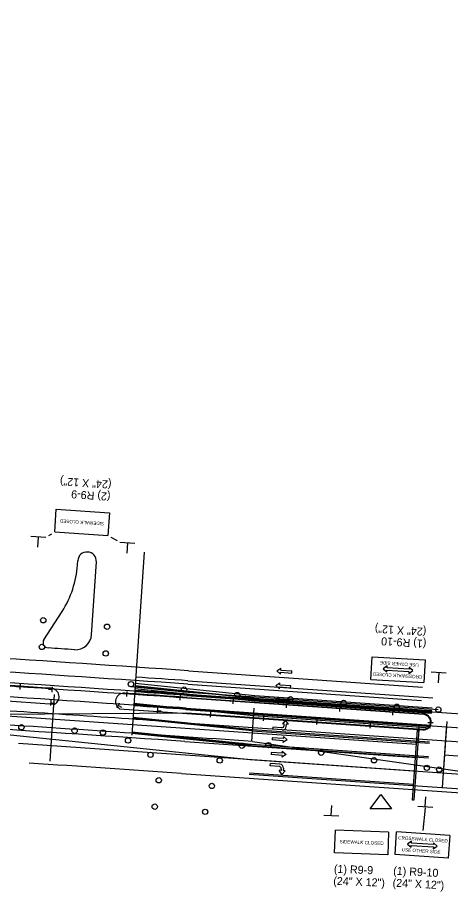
# Model space of a CAD drawing. Extents: x 659657 to 668193, y 633084 to 648639.
# Drawn here: x 660807 to 661132, y 642379 to 643043 of the extents above; entities that cross this region are included whole.
import ezdxf

# ---------------------------------------------------------------- set-up
doc = ezdxf.new("R2010")
doc.units = 0
for name, color, linetype in [('R_Draft', 7, 'Continuous'), ('R_MOT_Stage 2', 7, 'Continuous'), ('R_MOT_Stage 2_Striping', 7, 'Continuous'), ('R_MOT_Stage 3', 7, 'Continuous'), ('R_MOT_Stage 3_Striping', 7, 'Continuous'), ('R_MOT_Stage 4', 7, 'Continuous'), ('R_MOT_Stage 4_Striping', 7, 'Continuous'), ('R_MOT_Stage 4_Striping_PPM', 7, 'Continuous'), ('R_MOT_Stage 5', 7, 'Continuous'), ('R_MOT_Stage 5_Striping', 7, 'Continuous'), ('R_MOT_Stage 5_Striping_PPM', 7, 'Continuous'), ('R_ROW Annot', 7, 'Continuous'), ('T_Notes', 7, 'Continuous'), ('T_SIGNAL CONTROL CABINET', 7, 'Continuous')]:
    doc.layers.add(name, color=color, linetype=linetype)

msp = doc.modelspace()

# ---------------------------------------------------------------- linework, layer by layer
at = {"layer": 'R_Draft'}
for p, q in [((661072.13, 642547.16), (661073.2, 642564.14)), ((661073.2, 642564.14), (661112.98, 642561.65)), ((661112.98, 642561.65), (661111.92, 642544.68)), ((661117.44, 642552.85), (661128.67, 642552.15)), ((661123.01, 642552.34), (661122.54, 642544.67)), ((661072.13, 642547.16), (661111.92, 642544.68)), ((661042.54, 642445.15), (661042.84, 642452.82)), ((661048.13, 642444.77), (661036.89, 642445.21)), ((661044.96, 642417.35), (661045.62, 642434.34)), ((661085.45, 642432.81), (661045.62, 642434.34)), ((661085.45, 642432.81), (661084.79, 642415.81)), ((661084.79, 642415.81), (661044.96, 642417.35))]:
    msp.add_line(p, q, dxfattribs=at)
msp.add_lwpolyline([(661103.73, 642553.71), (661100.96, 642556.13), (661100.87, 642554.73), (661084.35, 642555.76), (661084.44, 642557.17), (661081.38, 642555.1), (661084.16, 642552.68), (661084.24, 642554.08), (661100.76, 642553.05), (661100.68, 642551.64)], close=True, dxfattribs=at)
at = {"layer": 'R_MOT_Stage 2'}
for centre in [(660810.22, 642511.3), (660850.14, 642508.74), (660871.33, 642507.33), (660890.14, 642501.35), (660975.54, 642497.5), (660995.36, 642497.86), (660907.03, 642490.63), (661034.95, 642492.21), (660958.88, 642486.43), (661074.55, 642486.56), (661114.15, 642480.92), (661123.44, 642479.59), (660913.2, 642471.61), (660952.95, 642467.33), (660910.18, 642451.84), (660948, 642447.95)]:
    msp.add_circle(centre, 2, dxfattribs=at)
at = {"layer": 'R_MOT_Stage 2_Striping'}
for p, q in [((660935.07, 642546.09), (661118.74, 642533.32)), ((660934.3, 642535.11), (661117.98, 642522.34)), ((660934.37, 642536.11), (661118.05, 642523.34)), ((660933.58, 642524.64), (661117.25, 642511.87)), ((660933.65, 642525.64), (661117.32, 642512.87)), ((660932.88, 642514.66), (661237.48, 642493.49)), ((660983.54, 642500.56), (661138.84, 642478.4)), ((661127.39, 642490.62), (661236.8, 642483.01))]:
    msp.add_line(p, q, dxfattribs=at)
for radius, start, end in [(22935.31, 86.023046, 86.121408), (22924.31, 86.023046, 86.121408), (22925.31, 86.023046, 86.121408), (22903.81, 86.023046, 86.444357), (22913.81, 86.023046, 86.121408), (22914.81, 86.023046, 86.121408), (22893.31, 85.894127, 86.444357)]:
    msp.add_arc((659344.38, 619666), radius, start, end, dxfattribs=at)
at = {"layer": 'R_MOT_Stage 3'}
for p, q in [((660895.48, 642544.22), (660985.14, 642535.09)), ((660985, 642533.09), (660895.34, 642542.23)), ((660985, 642533.09), (661117.88, 642523.85)), ((660985.14, 642535.09), (661118.02, 642525.85))]:
    msp.add_line(p, q, dxfattribs=at)
for centre in [(660826.63, 642591.39), (660874.44, 642586.52), (660825.62, 642571.41), (660873.43, 642566.55), (660892.38, 642543.53), (660932.17, 642539.48), (660971.97, 642535.43), (661011.87, 642532.23), (661051.77, 642529.45), (661091.67, 642526.68), (661122.73, 642524.52)]:
    msp.add_circle(centre, 2, dxfattribs=at)
at = {"layer": 'R_MOT_Stage 3_Striping'}
for p, q in [((660895.21, 642540.24), (660984.86, 642531.11)), ((660984.86, 642531.1), (661117.75, 642521.86)), ((660894.46, 642529.26), (660984.1, 642520.12)), ((660983.3, 642508.65), (660893.68, 642517.78)), ((660893.75, 642518.78), (660983.37, 642509.65)), ((660984.1, 642520.12), (661116.98, 642510.89)), ((660768.15, 642508.98), (660981.81, 642487.2)), ((660892.94, 642506.81), (660982.54, 642497.68)), ((660893.01, 642507.81), (660982.6, 642498.68)), ((660983.3, 642508.65), (661116.18, 642499.41)), ((660983.37, 642509.65), (661116.25, 642500.41)), ((660982.54, 642497.68), (661115.42, 642488.44)), ((660982.6, 642498.68), (661115.49, 642489.44)), ((660981.81, 642487.2), (661235.75, 642469.55)), ((660981.04, 642476.23), (661234.99, 642458.58))]:
    msp.add_line(p, q, dxfattribs=at)
at = {"layer": 'R_MOT_Stage 4'}
for p, q in [((660895.48, 642544.22), (660985.14, 642535.09)), ((660895.34, 642542.23), (660985, 642533.09)), ((660985, 642533.09), (661117.88, 642523.85)), ((660985.14, 642535.09), (661118.02, 642525.85))]:
    msp.add_line(p, q, dxfattribs=at)
for centre in [(660826.63, 642591.39), (660874.44, 642586.52), (660825.62, 642571.41), (660873.43, 642566.55), (660892.38, 642543.53), (660932.17, 642539.48), (660971.97, 642535.43), (661011.87, 642532.23), (661051.77, 642529.45), (661091.67, 642526.68), (661122.73, 642524.52)]:
    msp.add_circle(centre, 2, dxfattribs=at)
at = {"layer": 'R_MOT_Stage 4_Striping'}
for p, q in [((660895.21, 642540.24), (660985.11, 642531.08)), ((660985.11, 642531.08), (661117.75, 642521.86)), ((660894.46, 642529.26), (660984.1, 642520.12)), ((660983.3, 642508.65), (660893.68, 642517.78)), ((660893.75, 642518.78), (660983.37, 642509.65)), ((660984.1, 642520.12), (661116.98, 642510.89)), ((660768.15, 642508.98), (660981.81, 642487.2)), ((660982.54, 642497.68), (660892.94, 642506.81)), ((660893.01, 642507.81), (660982.6, 642498.68)), ((660983.3, 642508.65), (661116.18, 642499.41)), ((660983.37, 642509.65), (661116.25, 642500.41)), ((660982.54, 642497.68), (661115.42, 642488.44)), ((660982.6, 642498.68), (661115.49, 642489.44)), ((660981.81, 642487.2), (661235.75, 642469.55)), ((660981.04, 642476.23), (661235.44, 642458.55))]:
    msp.add_line(p, q, dxfattribs=at)
at = {"layer": 'R_MOT_Stage 4_Striping_PPM'}
msp.add_arc((660777.38, 642087.58), 954.93, 348.72774, 348.72774, dxfattribs=at)
at = {"layer": 'R_MOT_Stage 5'}
for p, q in [((660809.21, 642541.46), (660806.5, 642541.64)), ((660809.4, 642543.43), (660809.14, 642539.46)), ((660833.2, 642539.47), (660830.49, 642539.65)), ((660833.38, 642541.44), (660833.12, 642537.47)), ((660889.23, 642538.18), (660888.96, 642534.21)), ((660832.29, 642527.58), (660832.53, 642531.55)), ((660889.04, 642536.21), (660886.33, 642536.39)), ((660928.95, 642533.48), (660926.24, 642533.67)), ((660929.14, 642535.45), (660928.87, 642531.48)), ((660968.85, 642530.71), (660966.14, 642530.9)), ((660969.04, 642532.68), (660968.77, 642528.71)), ((660832.46, 642529.55), (660835.18, 642529.38)), ((660881.96, 642525.93), (660883.8, 642529.46)), ((660882.93, 642527.66), (660885.34, 642526.41)), ((660912.14, 642521.79), (660912.38, 642525.76)), ((660912.31, 642523.76), (660915.03, 642523.6)), ((661008.75, 642527.93), (661006.04, 642528.12)), ((661008.95, 642529.9), (661008.67, 642525.93)), ((661048.66, 642525.16), (661045.95, 642525.35)), ((661048.85, 642527.13), (661048.58, 642523.16)), ((661088.76, 642524.36), (661088.48, 642520.39)), ((660951.91, 642518.87), (660952.18, 642522.84)), ((660952.1, 642520.85), (660954.81, 642520.66)), ((660991.81, 642516.1), (660992.09, 642520.07)), ((660992.01, 642518.07), (660994.72, 642517.88)), ((661031.72, 642513.33), (661031.99, 642517.3)), ((661088.56, 642522.38), (661085.85, 642522.57)), ((661031.91, 642515.3), (661034.62, 642515.11)), ((661071.62, 642510.55), (661071.9, 642514.52)), ((661071.81, 642512.52), (661074.52, 642512.33)), ((661108.05, 642508.02), (661108.33, 642511.99)), ((661114.98, 642514.97), (661118.96, 642514.94)), ((661116.96, 642514.9), (661116.94, 642512.18)), ((661108.25, 642509.99), (661110.96, 642509.8))]:
    msp.add_line(p, q, dxfattribs=at)
at = {"layer": 'R_MOT_Stage 5_Striping'}
for p, q in [((660935.59, 642553.57), (661110.88, 642541.38)), ((660934.89, 642543.59), (661110.18, 642531.41)), ((660744.83, 642534.75), (660835.05, 642528.48)), ((660934.2, 642533.62), (661111.89, 642521.26)), ((660744.16, 642523.77), (661106.32, 642498.6)), ((660883.79, 642525.09), (661111.06, 642509.29)), ((660808.06, 642499.28), (661104.92, 642478.65)), ((660932.62, 642500.65), (661106.61, 642488.55)), ((660981.11, 642477.23), (661104.22, 642468.67))]:
    msp.add_line(p, q, dxfattribs=at)
msp.add_lwpolyline([(661103.41, 642456.69), (661107.08, 642509.57), (661108.06, 642509.5), (661104.39, 642456.63)], close=True, dxfattribs=at)
for centre, radius, start, end in [((659344.38, 619666), 22942.81, 86.023046, 86.818762), ((659344.38, 619666), 22932.81, 86.023046, 86.818762), ((659344.38, 619666), 22922.81, 86.277519, 86.818762), ((660832.21, 642534.14), 6.33, 296.70336, 86.27752), ((660887.09, 642530.5), 6.33, 86.14002, 238.66973), ((659344.38, 619666), 22922.81, 86.023046, 86.140018), ((659344.38, 619666), 22889.81, 86.021267, 86.818762), ((661111.47, 642515.28), 6, 266.02305, 86.02305)]:
    msp.add_arc(centre, radius, start, end, dxfattribs=at)
at = {"layer": 'R_MOT_Stage 5_Striping_PPM'}
for p, q in [((660852.22, 642632.79), (660852.43, 642635.97)), ((660862.82, 642580.56), (660866.4, 642635.05)), ((660827.09, 642576.83), (660840.76, 642598.06))]:
    msp.add_line(p, q, dxfattribs=at)
for centre, radius, start, end in [((660777.38, 642087.58), 954.93, 348.72774, 348.72774), ((660859.42, 642635.51), 7, 356.23877, 176.23877), ((660779.38, 642637.57), 73, 327.22594, 356.23877), ((660850.85, 642581.35), 12, 266.23877, 356.23877), ((660830.46, 642574.67), 4, 147.22594, 266.28845), ((659344.38, 619666), 22952.81, 86.238769, 86.288452)]:
    msp.add_arc(centre, radius, start, end, dxfattribs=at)
at = {"layer": 'R_ROW Annot'}
msp.add_lwpolyline([(661079.73, 642460.9), (661087.68, 642450.3), (661071.77, 642450.3)], close=True, dxfattribs=at)
at = {"layer": 'T_Notes'}
for p, q in [((660835.29, 642657.5), (660836.4, 642674.47)), ((660836.4, 642674.47), (660876.18, 642671.88)), ((660876.18, 642671.88), (660875.07, 642654.91)), ((660835.29, 642657.5), (660875.07, 642654.91)), ((660817.34, 642654.24), (660828.56, 642653.51)), ((660822.91, 642653.71), (660822.41, 642646.05)), ((660830.71, 642654.78), (660833.14, 642656.23)), ((660877.25, 642653.69), (660881.94, 642651.09)), ((660884.13, 642649.88), (660895.35, 642649.15)), ((660889.7, 642649.35), (660889.2, 642641.69)), ((661112.94, 642451.66), (661113.45, 642459.32)), ((661118.51, 642451.12), (661107.29, 642451.87)), ((661112.94, 642450.84), (661111.24, 642433.99)), ((661090.36, 642415.96), (661091.5, 642432.92)), ((661131.27, 642430.25), (661091.5, 642432.92)), ((661131.27, 642430.25), (661130.13, 642413.29)), ((661130.13, 642413.29), (661090.36, 642415.96))]:
    msp.add_line(p, q, dxfattribs=at)
for points in [[(661079.73, 642460.9), (661087.68, 642450.3), (661071.77, 642450.3)], [(661099.65, 642423.85), (661102.41, 642421.41), (661102.51, 642422.82), (661119.02, 642421.71), (661118.92, 642420.3), (661121.99, 642422.35), (661119.23, 642424.79), (661119.13, 642423.39), (661102.62, 642424.5), (661102.71, 642425.9)]]:
    msp.add_lwpolyline(points, close=True, dxfattribs=at)
at = {"layer": 'T_SIGNAL CONTROL CABINET'}
for p, q in [((660902.18, 642642.31), (660892.9, 642505.37)), ((661001.72, 642553.48), (661004.79, 642555.52)), ((661004.47, 642551.04), (661001.72, 642553.48)), ((661004.47, 642551.04), (661004.57, 642552.44)), ((661004.57, 642552.44), (661012.83, 642551.86)), ((661004.69, 642554.12), (661004.79, 642555.52)), ((661004.69, 642554.12), (661012.94, 642553.55)), ((661012.83, 642551.86), (661012.94, 642553.55)), ((661000.95, 642542.51), (661004.02, 642544.55)), ((661003.93, 642543.15), (661004.02, 642544.55)), ((660892.27, 642541.84), (660935.16, 642537.56)), ((660935.16, 642537.56), (661122.73, 642524.52)), ((661003.71, 642540.06), (661000.95, 642542.51)), ((661003.71, 642540.06), (661003.81, 642541.47)), ((661003.81, 642541.47), (661012.06, 642540.89)), ((661003.93, 642543.15), (661012.18, 642542.57)), ((661012.06, 642540.89), (661012.18, 642542.57)), ((660834.82, 642535.8), (660831.57, 642485.91)), ((661111.85, 642520.77), (660934.17, 642533.12)), ((660934.34, 642535.61), (661238.85, 642514.44)), ((660934.34, 642535.61), (661238.85, 642514.44)), ((661000.19, 642531.54), (661003.26, 642533.58)), ((661002.95, 642529.09), (661000.19, 642531.54)), ((661002.95, 642529.09), (661003.05, 642530.49)), ((661003.05, 642530.49), (661011.3, 642529.92)), ((661003.16, 642532.17), (661003.26, 642533.58)), ((661003.16, 642532.17), (661011.42, 642531.6)), ((661011.3, 642529.92), (661011.42, 642531.6)), ((660933.61, 642525.14), (661238.16, 642503.96)), ((660933.61, 642525.14), (661238.16, 642503.96)), ((660984.48, 642525.61), (660982.74, 642500.67)), ((660783.86, 642521.03), (660934.17, 642522.09)), ((660934.17, 642522.09), (661111.09, 642509.79)), ((660998.79, 642511.43), (660998.67, 642509.75)), ((661005.36, 642510.97), (660998.79, 642511.43)), ((661008.29, 642516.61), (661005.84, 642513.85)), ((661007.24, 642513.75), (661005.84, 642513.85)), ((661007.16, 642512.54), (661007.24, 642513.75)), ((661010.33, 642513.54), (661008.29, 642516.61)), ((661008.8, 642511.86), (661008.93, 642513.64)), ((661010.33, 642513.54), (661008.93, 642513.64)), ((661128.99, 642513.56), (661125.7, 642466.17)), ((661129.13, 642515.55), (661126.67, 642480.14)), ((661005.8, 642509.25), (660998.67, 642509.75)), ((661006.58, 642504.28), (661006.49, 642502.87)), ((661006.58, 642504.28), (661009.34, 642501.83)), ((660998.23, 642503.45), (660998.11, 642501.76)), ((661006.37, 642501.19), (660998.11, 642501.76)), ((661006.49, 642502.87), (660998.23, 642503.45)), ((661009.34, 642501.83), (661006.27, 642499.79)), ((661006.37, 642501.19), (661006.27, 642499.79)), ((660997.47, 642492.47), (660997.35, 642490.79)), ((661005.61, 642490.22), (660997.35, 642490.79)), ((661005.72, 642491.9), (660997.47, 642492.47)), ((661008.58, 642490.86), (661005.51, 642488.81)), ((661005.82, 642493.3), (661005.72, 642491.9)), ((661005.82, 642493.3), (661008.58, 642490.86)), ((660996.77, 642482.47), (660996.89, 642484.15)), ((661004.02, 642483.65), (660996.89, 642484.15)), ((661005.61, 642490.22), (661005.51, 642488.81)), ((661003.34, 642482.01), (660996.77, 642482.47)), ((661005.47, 642476.02), (661003.42, 642479.09)), ((661004.83, 642478.99), (661003.42, 642479.09)), ((661004.91, 642480.21), (661004.83, 642478.99)), ((661007.91, 642478.78), (661005.47, 642476.02)), ((661006.63, 642480.65), (661006.51, 642478.88)), ((661007.91, 642478.78), (661006.51, 642478.88)), ((660930.25, 642476.75), (661234.78, 642455.58))]:
    msp.add_line(p, q, dxfattribs=at)
for centre, radius, start, end in [((659344.38, 619666), 22922.31, 86.023046, 86.818762), ((659344.38, 619666), 22924.81, 86.023046, 86.818762), ((659344.38, 619666), 22914.31, 86.023046, 86.818762), ((661111.47, 642515.28), 5.5, 266.02305, 86.02305), ((661005.47, 642512.66), 1.69, 266.02305, 356.02305), ((661006, 642512.05), 2.81, 266.02305, 356.02305), ((659344.38, 619666), 22865.81, 86.023046, 86.309975), ((661003.23, 642480.33), 1.69, 356.02305, 86.02305), ((661003.83, 642480.85), 2.81, 356.02305, 86.02305)]:
    msp.add_arc(centre, radius, start, end, dxfattribs=at)

# ---------------------------------------------------------------- texts
at = {"layer": 'R_Draft'}
for s, height, rotation, p in [('(24" X 12")', 6, 176.42134, (661113.92, 642585.62)), ('(1) R9-10', 6, 176.42134, (661113.92, 642576.62)), ('USE OTHER SIDE', 2.5, 176.42134, (661108.09, 642559.07)), ('CROSSWALK CLOSED', 2.5, 176.42134, (661110.79, 642550.13)), ('SIDEWALK CLOSED', 2.5, 357.78995, (661048.75, 642424.46)), ('(1) R9-9', 6, 357.78995, (661044.38, 642402.36)), ('(24" X 12")', 6, 357.78995, (661043.92, 642393.36))]:
    msp.add_text(s, height=height, rotation=rotation, dxfattribs=at).set_placement(p)
at = {"layer": 'T_Notes'}
for s, height, rotation, p in [('(24" X 12")', 6, 176.26311, (660877.92, 642695.86)), ('(2) R9-9', 6, 176.26311, (660877.15, 642686.84)), ('SIDEWALK CLOSED', 2.5, 176.26311, (660872.2, 642664.87)), ('CROSSWALK CLOSED', 2.5, 356.15887, (661092.6, 642427.46)), ('USE OTHER SIDE', 2.5, 356.15887, (661095.26, 642418.51)), ('(1) R9-10', 6, 357.05919, (661088.81, 642400.96)), ('(24" X 12")', 6, 357.05919, (661088.35, 642391.98))]:
    msp.add_text(s, height=height, rotation=rotation, dxfattribs=at).set_placement(p)

doc.saveas('drawing.dxf')
